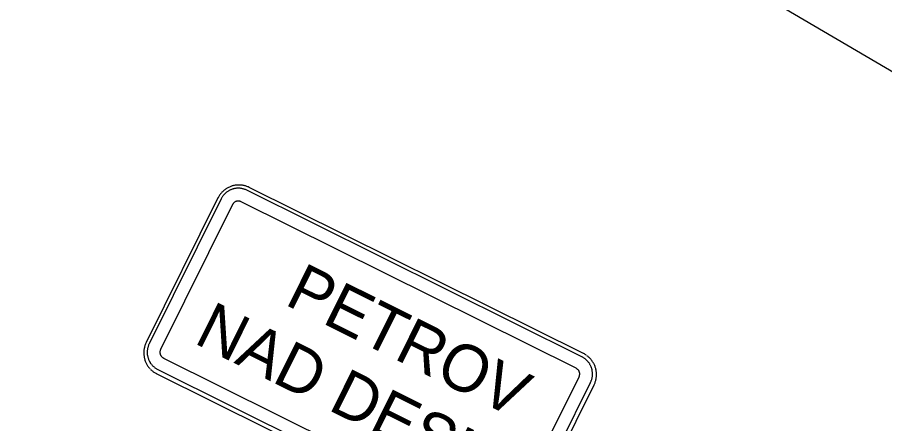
# Model space of a CAD drawing. Extents: x -559605 to -559051, y -1075984 to -1075185.
# Drawn here: x -559138.08 to -559123.61, y -1075223.48 to -1075216.7 of the extents above; entities that cross this region are included whole.
import ezdxf

# ---------------------------------------------------------------- set-up
doc = ezdxf.new("R2010")
doc.units = 0
doc.layers.add('Ramecek_rozpiska', color=7, linetype='Continuous')
doc.layers.add('Svisle DZ stavajici', color=7, linetype='Continuous')

msp = doc.modelspace()

# ---------------------------------------------------------------- linework, layer by layer
at = {"layer": 'Ramecek_rozpiska'}
msp.add_line((-559050.892, -1075260.275), (-559178.917, -1075185.029), dxfattribs=at)
at = {"layer": 'Svisle DZ stavajici'}
for p, q in [((-559134.435, -1075219.554), (-559134.445, -1075219.556)), ((-559134.425, -1075219.553), (-559134.435, -1075219.554)), ((-559134.414, -1075219.552), (-559134.425, -1075219.553)), ((-559134.404, -1075219.552), (-559134.414, -1075219.552)), ((-559134.394, -1075219.551), (-559134.404, -1075219.552)), ((-559134.383, -1075219.552), (-559134.394, -1075219.551)), ((-559134.373, -1075219.552), (-559134.383, -1075219.552)), ((-559134.363, -1075219.553), (-559134.373, -1075219.552)), ((-559134.353, -1075219.555), (-559134.363, -1075219.553)), ((-559134.657, -1075219.691), (-559134.663, -1075219.699)), ((-559134.651, -1075219.683), (-559134.657, -1075219.691)), ((-559134.645, -1075219.675), (-559134.651, -1075219.683)), ((-559134.638, -1075219.667), (-559134.645, -1075219.675)), ((-559134.63, -1075219.659), (-559134.638, -1075219.667)), ((-559134.624, -1075219.651), (-559134.63, -1075219.659)), ((-559134.617, -1075219.644), (-559134.624, -1075219.651)), ((-559134.61, -1075219.637), (-559134.617, -1075219.644)), ((-559134.602, -1075219.629), (-559134.61, -1075219.637)), ((-559134.595, -1075219.623), (-559134.602, -1075219.629)), ((-559134.587, -1075219.617), (-559134.595, -1075219.623)), ((-559134.579, -1075219.61), (-559134.587, -1075219.617)), ((-559134.57, -1075219.604), (-559134.579, -1075219.61)), ((-559134.561, -1075219.599), (-559134.57, -1075219.604)), ((-559134.552, -1075219.594), (-559134.561, -1075219.599)), ((-559134.543, -1075219.588), (-559134.552, -1075219.594)), ((-559134.534, -1075219.584), (-559134.543, -1075219.588)), ((-559134.524, -1075219.58), (-559134.534, -1075219.584)), ((-559134.515, -1075219.576), (-559134.524, -1075219.58)), ((-559134.505, -1075219.572), (-559134.515, -1075219.576)), ((-559134.495, -1075219.569), (-559134.505, -1075219.572)), ((-559134.486, -1075219.566), (-559134.495, -1075219.569)), ((-559134.476, -1075219.563), (-559134.486, -1075219.566)), ((-559134.466, -1075219.56), (-559134.476, -1075219.563)), ((-559134.456, -1075219.558), (-559134.466, -1075219.56)), ((-559134.445, -1075219.556), (-559134.456, -1075219.558)), ((-559134.343, -1075219.556), (-559134.353, -1075219.555)), ((-559134.333, -1075219.559), (-559134.343, -1075219.556)), ((-559134.323, -1075219.561), (-559134.333, -1075219.559)), ((-559134.313, -1075219.563), (-559134.323, -1075219.561)), ((-559134.302, -1075219.565), (-559134.313, -1075219.563)), ((-559134.292, -1075219.568), (-559134.302, -1075219.565)), ((-559134.282, -1075219.572), (-559134.292, -1075219.568)), ((-559134.272, -1075219.575), (-559134.282, -1075219.572)), ((-559134.262, -1075219.58), (-559134.272, -1075219.575)), ((-559134.252, -1075219.584), (-559134.262, -1075219.58)), ((-559134.251, -1075219.584), (-559134.252, -1075219.584)), ((-559134.249, -1075219.585), (-559134.251, -1075219.584)), ((-559128.659, -1075222.362), (-559134.249, -1075219.585)), ((-559134.68, -1075219.728), (-559135.881, -1075222.145)), ((-559134.488, -1075219.823), (-559135.689, -1075222.24)), ((-559134.679, -1075219.726), (-559134.68, -1075219.728)), ((-559134.68, -1075219.728), (-559134.68, -1075219.728)), ((-559134.674, -1075219.717), (-559134.679, -1075219.726)), ((-559134.669, -1075219.708), (-559134.674, -1075219.717)), ((-559134.663, -1075219.699), (-559134.669, -1075219.708)), ((-559134.485, -1075219.818), (-559134.488, -1075219.823)), ((-559134.481, -1075219.812), (-559134.485, -1075219.818)), ((-559134.477, -1075219.806), (-559134.481, -1075219.812)), ((-559134.474, -1075219.8), (-559134.477, -1075219.806)), ((-559134.469, -1075219.796), (-559134.474, -1075219.8)), ((-559134.464, -1075219.792), (-559134.469, -1075219.796)), ((-559134.458, -1075219.787), (-559134.464, -1075219.792)), ((-559134.454, -1075219.783), (-559134.458, -1075219.787)), ((-559134.447, -1075219.78), (-559134.454, -1075219.783)), ((-559134.441, -1075219.777), (-559134.447, -1075219.78)), ((-559134.438, -1075219.775), (-559134.441, -1075219.777)), ((-559134.434, -1075219.774), (-559134.438, -1075219.775)), ((-559134.43, -1075219.773), (-559134.434, -1075219.774)), ((-559134.427, -1075219.772), (-559134.43, -1075219.773)), ((-559134.424, -1075219.771), (-559134.427, -1075219.772)), ((-559134.42, -1075219.769), (-559134.424, -1075219.771)), ((-559134.417, -1075219.768), (-559134.42, -1075219.769)), ((-559134.413, -1075219.767), (-559134.417, -1075219.768)), ((-559134.407, -1075219.766), (-559134.413, -1075219.767)), ((-559134.399, -1075219.765), (-559134.407, -1075219.766)), ((-559134.393, -1075219.766), (-559134.399, -1075219.765)), ((-559134.386, -1075219.766), (-559134.393, -1075219.766)), ((-559134.383, -1075219.766), (-559134.386, -1075219.766)), ((-559134.38, -1075219.767), (-559134.383, -1075219.766)), ((-559134.377, -1075219.767), (-559134.38, -1075219.767)), ((-559134.374, -1075219.769), (-559134.377, -1075219.767)), ((-559134.367, -1075219.77), (-559134.374, -1075219.769)), ((-559134.36, -1075219.771), (-559134.367, -1075219.77)), ((-559134.353, -1075219.773), (-559134.36, -1075219.771)), ((-559134.347, -1075219.776), (-559134.353, -1075219.773)), ((-559134.345, -1075219.777), (-559134.347, -1075219.776)), ((-559134.347, -1075219.776), (-559134.347, -1075219.776)), ((-559128.754, -1075222.554), (-559134.345, -1075219.777)), ((-559135.886, -1075222.157), (-559135.89, -1075222.166)), ((-559135.882, -1075222.147), (-559135.886, -1075222.157)), ((-559135.881, -1075222.145), (-559135.882, -1075222.147)), ((-559135.912, -1075222.266), (-559135.913, -1075222.277)), ((-559135.913, -1075222.277), (-559135.913, -1075222.287)), ((-559135.913, -1075222.287), (-559135.913, -1075222.297)), ((-559135.913, -1075222.297), (-559135.913, -1075222.307)), ((-559135.911, -1075222.256), (-559135.912, -1075222.266)), ((-559135.91, -1075222.246), (-559135.911, -1075222.256)), ((-559135.908, -1075222.236), (-559135.91, -1075222.246)), ((-559135.906, -1075222.226), (-559135.908, -1075222.236)), ((-559135.904, -1075222.216), (-559135.906, -1075222.226)), ((-559135.902, -1075222.205), (-559135.904, -1075222.216)), ((-559135.899, -1075222.195), (-559135.902, -1075222.205)), ((-559135.896, -1075222.185), (-559135.899, -1075222.195)), ((-559135.893, -1075222.176), (-559135.896, -1075222.185)), ((-559135.89, -1075222.166), (-559135.893, -1075222.176)), ((-559135.7, -1075222.281), (-559135.701, -1075222.288)), ((-559135.701, -1075222.288), (-559135.701, -1075222.294)), ((-559135.701, -1075222.294), (-559135.7, -1075222.302)), ((-559135.699, -1075222.265), (-559135.7, -1075222.273)), ((-559135.7, -1075222.273), (-559135.7, -1075222.281)), ((-559135.7, -1075222.302), (-559135.698, -1075222.308)), ((-559135.696, -1075222.26), (-559135.699, -1075222.265)), ((-559135.694, -1075222.254), (-559135.696, -1075222.26)), ((-559135.692, -1075222.247), (-559135.694, -1075222.254)), ((-559135.689, -1075222.24), (-559135.692, -1075222.247)), ((-559135.913, -1075222.307), (-559135.912, -1075222.318)), ((-559135.912, -1075222.318), (-559135.911, -1075222.328)), ((-559135.911, -1075222.328), (-559135.909, -1075222.338)), ((-559135.909, -1075222.338), (-559135.907, -1075222.349)), ((-559135.907, -1075222.349), (-559135.904, -1075222.359)), ((-559135.904, -1075222.359), (-559135.902, -1075222.369)), ((-559135.902, -1075222.369), (-559135.899, -1075222.379)), ((-559135.899, -1075222.379), (-559135.895, -1075222.388)), ((-559135.895, -1075222.388), (-559135.893, -1075222.398)), ((-559135.893, -1075222.398), (-559135.889, -1075222.408)), ((-559135.889, -1075222.408), (-559135.885, -1075222.418)), ((-559135.885, -1075222.418), (-559135.881, -1075222.428)), ((-559135.881, -1075222.428), (-559135.876, -1075222.437)), ((-559135.876, -1075222.437), (-559135.872, -1075222.446)), ((-559135.872, -1075222.446), (-559135.866, -1075222.454)), ((-559135.698, -1075222.308), (-559135.696, -1075222.315)), ((-559135.696, -1075222.315), (-559135.694, -1075222.322)), ((-559135.694, -1075222.322), (-559135.691, -1075222.328)), ((-559135.691, -1075222.328), (-559135.689, -1075222.334)), ((-559135.689, -1075222.334), (-559135.685, -1075222.34)), ((-559135.685, -1075222.34), (-559135.682, -1075222.346)), ((-559135.682, -1075222.346), (-559135.678, -1075222.352)), ((-559135.678, -1075222.352), (-559135.674, -1075222.358)), ((-559135.674, -1075222.358), (-559135.669, -1075222.362)), ((-559135.669, -1075222.362), (-559135.665, -1075222.367)), ((-559135.665, -1075222.367), (-559135.662, -1075222.369)), ((-559135.662, -1075222.369), (-559135.66, -1075222.372)), ((-559135.66, -1075222.372), (-559135.657, -1075222.373)), ((-559135.657, -1075222.373), (-559135.654, -1075222.375)), ((-559135.654, -1075222.375), (-559135.647, -1075222.379)), ((-559135.647, -1075222.379), (-559135.642, -1075222.382)), ((-559135.642, -1075222.382), (-559135.641, -1075222.382)), ((-559135.641, -1075222.382), (-559135.639, -1075222.383)), ((-559135.639, -1075222.383), (-559130.049, -1075225.16)), ((-559128.657, -1075222.363), (-559128.659, -1075222.362)), ((-559128.648, -1075222.368), (-559128.657, -1075222.363)), ((-559128.657, -1075222.363), (-559128.657, -1075222.363)), ((-559128.639, -1075222.374), (-559128.648, -1075222.368)), ((-559128.631, -1075222.379), (-559128.639, -1075222.374)), ((-559128.622, -1075222.385), (-559128.631, -1075222.379)), ((-559128.614, -1075222.391), (-559128.622, -1075222.385)), ((-559128.606, -1075222.398), (-559128.614, -1075222.391)), ((-559128.598, -1075222.405), (-559128.606, -1075222.398)), ((-559128.59, -1075222.412), (-559128.598, -1075222.405)), ((-559128.582, -1075222.418), (-559128.59, -1075222.412)), ((-559128.574, -1075222.426), (-559128.582, -1075222.418)), ((-559128.567, -1075222.433), (-559128.574, -1075222.426)), ((-559128.56, -1075222.44), (-559128.567, -1075222.433)), ((-559128.552, -1075222.448), (-559128.56, -1075222.44)), ((-559128.546, -1075222.456), (-559128.552, -1075222.448)), ((-559135.866, -1075222.454), (-559135.861, -1075222.463)), ((-559135.861, -1075222.463), (-559135.855, -1075222.472)), ((-559135.855, -1075222.472), (-559135.848, -1075222.48)), ((-559135.848, -1075222.48), (-559135.842, -1075222.488)), ((-559135.842, -1075222.488), (-559135.836, -1075222.496)), ((-559135.836, -1075222.496), (-559135.829, -1075222.504)), ((-559135.829, -1075222.504), (-559135.822, -1075222.511)), ((-559135.822, -1075222.511), (-559135.815, -1075222.519)), ((-559135.815, -1075222.519), (-559135.807, -1075222.526)), ((-559135.807, -1075222.526), (-559135.799, -1075222.532)), ((-559135.799, -1075222.532), (-559135.791, -1075222.538)), ((-559135.791, -1075222.538), (-559135.783, -1075222.545)), ((-559135.783, -1075222.545), (-559135.774, -1075222.551)), ((-559135.774, -1075222.551), (-559135.765, -1075222.557)), ((-559135.765, -1075222.557), (-559135.756, -1075222.562)), ((-559135.756, -1075222.562), (-559135.746, -1075222.568)), ((-559135.746, -1075222.568), (-559135.737, -1075222.573)), ((-559135.737, -1075222.573), (-559135.736, -1075222.573)), ((-559135.736, -1075222.573), (-559135.734, -1075222.574)), ((-559135.734, -1075222.574), (-559130.144, -1075225.351)), ((-559128.752, -1075222.555), (-559128.754, -1075222.554)), ((-559128.754, -1075222.554), (-559128.754, -1075222.554)), ((-559128.747, -1075222.558), (-559128.752, -1075222.555)), ((-559128.741, -1075222.562), (-559128.747, -1075222.558)), ((-559128.736, -1075222.567), (-559128.741, -1075222.562)), ((-559128.73, -1075222.572), (-559128.736, -1075222.567)), ((-559128.727, -1075222.574), (-559128.73, -1075222.572)), ((-559128.725, -1075222.576), (-559128.727, -1075222.574)), ((-559128.723, -1075222.578), (-559128.725, -1075222.576)), ((-559128.721, -1075222.58), (-559128.723, -1075222.578)), ((-559128.717, -1075222.585), (-559128.721, -1075222.58)), ((-559128.712, -1075222.59), (-559128.717, -1075222.585)), ((-559128.708, -1075222.597), (-559128.712, -1075222.59)), ((-559128.54, -1075222.465), (-559128.546, -1075222.456)), ((-559128.533, -1075222.473), (-559128.54, -1075222.465)), ((-559128.528, -1075222.482), (-559128.533, -1075222.473)), ((-559128.524, -1075222.49), (-559128.528, -1075222.482)), ((-559128.519, -1075222.5), (-559128.524, -1075222.49)), ((-559128.515, -1075222.509), (-559128.519, -1075222.5)), ((-559128.506, -1075222.528), (-559128.515, -1075222.509)), ((-559128.498, -1075222.548), (-559128.506, -1075222.528)), ((-559128.495, -1075222.558), (-559128.498, -1075222.548)), ((-559128.492, -1075222.568), (-559128.495, -1075222.558)), ((-559128.49, -1075222.577), (-559128.492, -1075222.568)), ((-559128.488, -1075222.587), (-559128.49, -1075222.577)), ((-559128.486, -1075222.597), (-559128.488, -1075222.587)), ((-559129.905, -1075225.113), (-559128.705, -1075222.697)), ((-559128.705, -1075222.603), (-559128.708, -1075222.597)), ((-559128.704, -1075222.606), (-559128.705, -1075222.603)), ((-559128.705, -1075222.697), (-559128.702, -1075222.691)), ((-559128.703, -1075222.61), (-559128.704, -1075222.606)), ((-559128.702, -1075222.613), (-559128.703, -1075222.61)), ((-559128.701, -1075222.617), (-559128.702, -1075222.613)), ((-559128.702, -1075222.691), (-559128.7, -1075222.684)), ((-559128.699, -1075222.62), (-559128.701, -1075222.617)), ((-559128.7, -1075222.684), (-559128.699, -1075222.677)), ((-559128.698, -1075222.623), (-559128.699, -1075222.62)), ((-559128.699, -1075222.677), (-559128.697, -1075222.67)), ((-559128.697, -1075222.627), (-559128.698, -1075222.623)), ((-559128.697, -1075222.63), (-559128.697, -1075222.627)), ((-559128.696, -1075222.633), (-559128.697, -1075222.63)), ((-559128.697, -1075222.663), (-559128.696, -1075222.657)), ((-559128.697, -1075222.67), (-559128.697, -1075222.663)), ((-559128.696, -1075222.637), (-559128.696, -1075222.633)), ((-559128.696, -1075222.64), (-559128.696, -1075222.637)), ((-559128.696, -1075222.643), (-559128.696, -1075222.64)), ((-559128.696, -1075222.65), (-559128.696, -1075222.643)), ((-559128.696, -1075222.657), (-559128.696, -1075222.65)), ((-559128.495, -1075222.741), (-559128.492, -1075222.731)), ((-559128.492, -1075222.731), (-559128.49, -1075222.721)), ((-559128.49, -1075222.721), (-559128.488, -1075222.711)), ((-559128.488, -1075222.711), (-559128.485, -1075222.701)), ((-559128.485, -1075222.608), (-559128.486, -1075222.597)), ((-559128.484, -1075222.618), (-559128.485, -1075222.608)), ((-559128.485, -1075222.701), (-559128.484, -1075222.691)), ((-559128.483, -1075222.628), (-559128.484, -1075222.618)), ((-559128.484, -1075222.691), (-559128.482, -1075222.681)), ((-559128.482, -1075222.639), (-559128.483, -1075222.628)), ((-559128.482, -1075222.65), (-559128.482, -1075222.639)), ((-559128.481, -1075222.66), (-559128.482, -1075222.65)), ((-559128.482, -1075222.67), (-559128.481, -1075222.66)), ((-559128.482, -1075222.681), (-559128.482, -1075222.67)), ((-559129.716, -1075225.207), (-559128.515, -1075222.791)), ((-559128.515, -1075222.79), (-559128.514, -1075222.788)), ((-559128.515, -1075222.791), (-559128.515, -1075222.79)), ((-559128.514, -1075222.788), (-559128.51, -1075222.779)), ((-559128.51, -1075222.779), (-559128.506, -1075222.769)), ((-559128.506, -1075222.769), (-559128.502, -1075222.76)), ((-559128.502, -1075222.76), (-559128.499, -1075222.751)), ((-559128.499, -1075222.751), (-559128.495, -1075222.741))]:
    msp.add_line(p, q, dxfattribs=at)
for points in [[(-559128.586, -1075222.337), (-559128.596, -1075222.329), (-559128.607, -1075222.323), (-559128.618, -1075222.316), (-559128.629, -1075222.31), (-559128.63, -1075222.31), (-559128.632, -1075222.309), (-559134.209, -1075219.539), (-559134.211, -1075219.538), (-559134.213, -1075219.536), (-559134.225, -1075219.531), (-559134.236, -1075219.527), (-559134.248, -1075219.522), (-559134.26, -1075219.518), (-559134.272, -1075219.514), (-559134.284, -1075219.51), (-559134.297, -1075219.507), (-559134.309, -1075219.504), (-559134.321, -1075219.502), (-559134.334, -1075219.5), (-559134.346, -1075219.499), (-559134.358, -1075219.498), (-559134.371, -1075219.498), (-559134.383, -1075219.498), (-559134.396, -1075219.499), (-559134.409, -1075219.5), (-559134.422, -1075219.501), (-559134.434, -1075219.502), (-559134.447, -1075219.503), (-559134.459, -1075219.505), (-559134.471, -1075219.507), (-559134.484, -1075219.51), (-559134.496, -1075219.513), (-559134.508, -1075219.517), (-559134.519, -1075219.522), (-559134.531, -1075219.526), (-559134.542, -1075219.532), (-559134.554, -1075219.537), (-559134.565, -1075219.543), (-559134.576, -1075219.549), (-559134.587, -1075219.556), (-559134.597, -1075219.563), (-559134.608, -1075219.57), (-559134.619, -1075219.577), (-559134.629, -1075219.585), (-559134.638, -1075219.593), (-559134.647, -1075219.601), (-559134.656, -1075219.61), (-559134.666, -1075219.618), (-559134.674, -1075219.627), (-559134.682, -1075219.637), (-559134.69, -1075219.647), (-559134.698, -1075219.657), (-559134.705, -1075219.668), (-559134.713, -1075219.678), (-559134.719, -1075219.689), (-559134.725, -1075219.7), (-559134.731, -1075219.711), (-559134.732, -1075219.713), (-559134.732, -1075219.713), (-559135.93, -1075222.124), (-559135.931, -1075222.125), (-559135.931, -1075222.126), (-559135.936, -1075222.138), (-559135.941, -1075222.149), (-559135.946, -1075222.161), (-559135.95, -1075222.173), (-559135.954, -1075222.185), (-559135.957, -1075222.198), (-559135.96, -1075222.21), (-559135.963, -1075222.222), (-559135.966, -1075222.234), (-559135.968, -1075222.247), (-559135.969, -1075222.259), (-559135.97, -1075222.272), (-559135.971, -1075222.285), (-559135.971, -1075222.298), (-559135.969, -1075222.31), (-559135.968, -1075222.322), (-559135.967, -1075222.335), (-559135.966, -1075222.347), (-559135.964, -1075222.36), (-559135.962, -1075222.373), (-559135.96, -1075222.385), (-559135.957, -1075222.397), (-559135.954, -1075222.409), (-559135.951, -1075222.421), (-559135.947, -1075222.433), (-559135.942, -1075222.445), (-559135.937, -1075222.457), (-559135.931, -1075222.468), (-559135.925, -1075222.479), (-559135.919, -1075222.49), (-559135.913, -1075222.502), (-559135.906, -1075222.513), (-559135.899, -1075222.523), (-559135.891, -1075222.533), (-559135.883, -1075222.543), (-559135.876, -1075222.553), (-559135.867, -1075222.562)], [(-559129.652, -1075225.243), (-559128.454, -1075222.832), (-559128.454, -1075222.831), (-559128.453, -1075222.829), (-559128.448, -1075222.818), (-559128.444, -1075222.807), (-559128.439, -1075222.795), (-559128.435, -1075222.783), (-559128.431, -1075222.77), (-559128.428, -1075222.758), (-559128.426, -1075222.745), (-559128.423, -1075222.732), (-559128.421, -1075222.72), (-559128.419, -1075222.708), (-559128.418, -1075222.696), (-559128.417, -1075222.683), (-559128.416, -1075222.671), (-559128.416, -1075222.659), (-559128.416, -1075222.646), (-559128.416, -1075222.633), (-559128.417, -1075222.621), (-559128.419, -1075222.608), (-559128.421, -1075222.596), (-559128.423, -1075222.583), (-559128.425, -1075222.571), (-559128.428, -1075222.558), (-559128.432, -1075222.546), (-559128.436, -1075222.533), (-559128.44, -1075222.522), (-559128.444, -1075222.51), (-559128.448, -1075222.499), (-559128.454, -1075222.488), (-559128.46, -1075222.477), (-559128.466, -1075222.467), (-559128.473, -1075222.456), (-559128.48, -1075222.446), (-559128.487, -1075222.434), (-559128.494, -1075222.424), (-559128.502, -1075222.413), (-559128.51, -1075222.403), (-559128.519, -1075222.393), (-559128.528, -1075222.384), (-559128.537, -1075222.376), (-559128.546, -1075222.367), (-559128.556, -1075222.359), (-559128.566, -1075222.351), (-559128.575, -1075222.344)], [(-559135.859, -1075222.571), (-559135.85, -1075222.579), (-559135.841, -1075222.588), (-559135.831, -1075222.595), (-559135.821, -1075222.603), (-559135.811, -1075222.611), (-559135.8, -1075222.618), (-559135.79, -1075222.626), (-559135.779, -1075222.632), (-559135.768, -1075222.638), (-559135.757, -1075222.644), (-559135.755, -1075222.645), (-559135.753, -1075222.647)], [(-559135.753, -1075222.647), (-559130.176, -1075225.417)]]:
    msp.add_lwpolyline(points, dxfattribs=at)

# ---------------------------------------------------------------- texts
for s, p in [('PETROV', (-559133.639, -1075221.481)), ('NAD DESNOU', (-559135.154, -1075222.125))]:
    msp.add_text(s, height=0.7823, rotation=333.5829, dxfattribs=at).set_placement(p)

doc.saveas('drawing.dxf')
